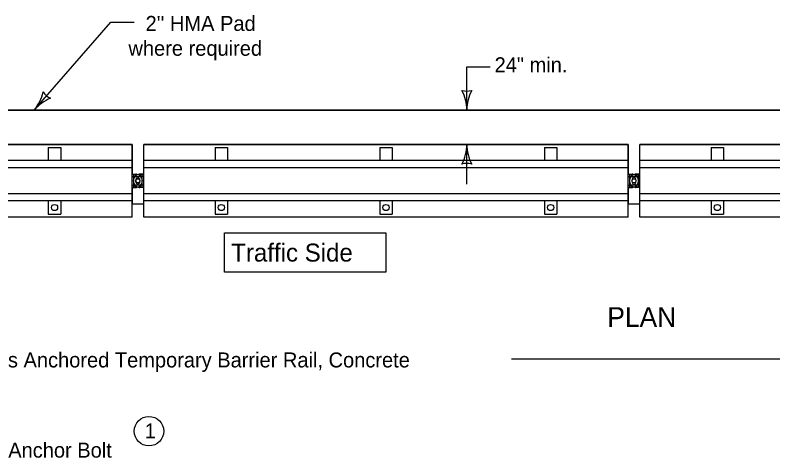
# Model space of a CAD drawing. Extents: x -2137026 to -2131464, y -2138478 to -2136524.
# Drawn here: x -2136307 to -2135538, y -2137950 to -2137501 of the extents above; entities that cross this region are included whole.
import ezdxf

# ---------------------------------------------------------------- set-up
doc = ezdxf.new("R2010")
doc.units = 0
for name, color, linetype in [('Level 2', 7, 'Continuous'), ('Level 3', 7, 'Continuous'), ('Level 41', 7, 'Continuous'), ('Level 9', 7, 'Continuous')]:
    doc.layers.add(name, color=color, linetype=linetype)

msp = doc.modelspace()

# ---------------------------------------------------------------- linework, layer by layer
at = {"layer": 'Level 2'}
for p, q in [((-2136287.84, -2137597.41), (-2136209.93, -2137508.05)), ((-2136209.93, -2137508.05), (-2136186.33, -2137508.05)), ((-2135848.76, -2137597.41), (-2135848.76, -2137553.36)), ((-2135848.76, -2137553.36), (-2135825.16, -2137553.36)), ((-2136188.5, -2137632.29), (-2136680.02, -2137632.29)), ((-2136188.5, -2137706.01), (-2136188.5, -2137632.29)), ((-2135685.1, -2137632.29), (-2136176.62, -2137632.29)), ((-2136176.62, -2137706.01), (-2136176.62, -2137632.29)), ((-2135848.76, -2137672.65), (-2135848.76, -2137632.29)), ((-2135685.1, -2137706.01), (-2135685.1, -2137632.29)), ((-2135181.7, -2137632.29), (-2135673.22, -2137632.29)), ((-2135673.22, -2137706.01), (-2135673.22, -2137632.29)), ((-2136188.5, -2137648.67), (-2136680.02, -2137648.67)), ((-2135685.1, -2137648.67), (-2136176.62, -2137648.67)), ((-2135181.7, -2137648.67), (-2135673.22, -2137648.67)), ((-2136188.5, -2137656.04), (-2136680.02, -2137656.04)), ((-2135685.1, -2137656.04), (-2136176.62, -2137656.04)), ((-2135181.7, -2137656.04), (-2135673.22, -2137656.04)), ((-2136188.5, -2137682.26), (-2136680.02, -2137682.26)), ((-2135685.1, -2137682.26), (-2136176.62, -2137682.26)), ((-2135181.7, -2137682.26), (-2135673.22, -2137682.26)), ((-2136188.5, -2137689.63), (-2136680.02, -2137689.63)), ((-2135685.1, -2137689.63), (-2136176.62, -2137689.63)), ((-2135181.7, -2137689.63), (-2135673.22, -2137689.63)), ((-2136188.5, -2137706.01), (-2136680.02, -2137706.01)), ((-2135685.1, -2137706.01), (-2136176.62, -2137706.01)), ((-2135181.7, -2137706.01), (-2135673.22, -2137706.01)), ((-2135803.58, -2137849.7), (-2134672.37, -2137849.7))]:
    msp.add_line(p, q, dxfattribs=at)
msp.add_circle((-2136171.3, -2137923.14), 15, dxfattribs=at)
for centre, radius, start, end in [((-2136320.19, -2137569.84), 42.5, 319.56638, 347.63887), ((-2136264.73, -2137570.28), 16.42, 211.83303, 247.29973), ((-2135848.76, -2137561.77), 16.42, 252.26665, 287.73335), ((-2135891.26, -2137597.41), 42.5, 360, 28.07249), ((-2135806.26, -2137597.41), 42.5, 151.92751, 180), ((-2136255.49, -2137624.97), 42.5, 111.49389, 139.56638), ((-2135891.26, -2137632.29), 42.5, 331.92751, 360), ((-2135806.26, -2137632.29), 42.5, 180, 208.07249), ((-2135848.76, -2137667.92), 16.42, 72.26665, 107.73335)]:
    msp.add_arc(centre, radius, start, end, dxfattribs=at)
at = {"layer": 'Level 41'}
for p, q in [((-2136273.44, -2137635.41), (-2136273.44, -2137648.67)), ((-2136273.44, -2137635.41), (-2136260.85, -2137635.41)), ((-2136260.85, -2137635.41), (-2136260.85, -2137648.67)), ((-2136104.27, -2137635.41), (-2136091.69, -2137635.41)), ((-2136104.27, -2137635.41), (-2136104.27, -2137648.67)), ((-2136091.69, -2137635.41), (-2136091.69, -2137648.67)), ((-2135937.15, -2137635.41), (-2135924.57, -2137635.41)), ((-2135937.15, -2137635.41), (-2135937.15, -2137648.67)), ((-2135924.57, -2137635.41), (-2135924.57, -2137648.67)), ((-2135770.04, -2137635.41), (-2135770.04, -2137648.67)), ((-2135770.04, -2137635.41), (-2135757.45, -2137635.41)), ((-2135757.45, -2137635.41), (-2135757.45, -2137648.67)), ((-2135600.87, -2137635.41), (-2135588.29, -2137635.41)), ((-2135600.87, -2137635.41), (-2135600.87, -2137648.67)), ((-2135588.29, -2137635.41), (-2135588.29, -2137648.67)), ((-2136188.5, -2137662.47), (-2136184.57, -2137662.47)), ((-2136188.5, -2137664.82), (-2136184.57, -2137664.82)), ((-2136176.62, -2137662.47), (-2136180.56, -2137662.47)), ((-2136176.62, -2137664.82), (-2136180.56, -2137664.82)), ((-2135685.1, -2137662.47), (-2135681.17, -2137662.47)), ((-2135685.1, -2137664.82), (-2135681.17, -2137664.82)), ((-2135673.22, -2137662.47), (-2135677.16, -2137662.47)), ((-2135673.22, -2137664.82), (-2135677.16, -2137664.82)), ((-2136188.5, -2137673.48), (-2136184.57, -2137673.48)), ((-2136176.62, -2137673.48), (-2136180.56, -2137673.48)), ((-2135685.1, -2137673.48), (-2135681.17, -2137673.48)), ((-2135673.22, -2137673.48), (-2135677.16, -2137673.48)), ((-2136188.5, -2137675.83), (-2136184.57, -2137675.83)), ((-2136176.62, -2137675.83), (-2136180.56, -2137675.83)), ((-2135685.1, -2137675.83), (-2135681.17, -2137675.83)), ((-2135673.22, -2137675.83), (-2135677.16, -2137675.83)), ((-2136273.44, -2137689.63), (-2136273.44, -2137702.89)), ((-2136260.85, -2137689.63), (-2136260.85, -2137702.89)), ((-2136104.27, -2137689.63), (-2136104.27, -2137702.89)), ((-2136091.69, -2137689.63), (-2136091.69, -2137702.89)), ((-2135937.15, -2137689.63), (-2135937.15, -2137702.89)), ((-2135924.57, -2137689.63), (-2135924.57, -2137702.89)), ((-2135770.04, -2137689.63), (-2135770.04, -2137702.89)), ((-2135757.45, -2137689.63), (-2135757.45, -2137702.89)), ((-2135600.87, -2137689.63), (-2135600.87, -2137702.89)), ((-2135588.29, -2137689.63), (-2135588.29, -2137702.89)), ((-2136273.44, -2137702.89), (-2136260.85, -2137702.89)), ((-2136104.27, -2137702.89), (-2136091.69, -2137702.89)), ((-2135937.15, -2137702.89), (-2135924.57, -2137702.89)), ((-2135770.04, -2137702.89), (-2135757.45, -2137702.89)), ((-2135600.87, -2137702.89), (-2135588.29, -2137702.89))]:
    msp.add_line(p, q, dxfattribs=at)
for centre in [(-2136267.14, -2137696.26), (-2136097.98, -2137696.26), (-2135930.86, -2137696.26), (-2135763.75, -2137696.26), (-2135594.58, -2137696.26)]:
    msp.add_circle(centre, 3.15, dxfattribs=at)
for centre, radius, start, end in [((-2136180.56, -2137669.15), 6.68, 90, 270), ((-2136180.56, -2137669.15), 4.33, 90, 270), ((-2136184.57, -2137669.15), 6.68, 270, 90), ((-2136184.57, -2137669.15), 4.33, 270, 90), ((-2135677.16, -2137669.15), 6.68, 90, 270), ((-2135677.16, -2137669.15), 4.33, 90, 270), ((-2135681.17, -2137669.15), 6.68, 270, 90), ((-2135681.17, -2137669.15), 4.33, 270, 90)]:
    msp.add_arc(centre, radius, start, end, dxfattribs=at)
at = {"layer": 'Level 9'}
for p, q in [((-2136691.9, -2137597.41), (-2134672.37, -2137597.41)), ((-2136191.5, -2137597.41), (-2136601.44, -2137597.41)), ((-2136601.44, -2137632.29), (-2136188.5, -2137632.29)), ((-2135673.22, -2137632.29), (-2135181.7, -2137632.29)), ((-2136188.5, -2137662.47), (-2136184.57, -2137662.47)), ((-2136186.66, -2137662.62), (-2136178.47, -2137662.62)), ((-2136186.66, -2137675.73), (-2136186.66, -2137662.62)), ((-2136183.13, -2137662.62), (-2136181.99, -2137662.62)), ((-2136180.56, -2137662.47), (-2136176.62, -2137662.47)), ((-2136178.47, -2137662.62), (-2136178.47, -2137675.73)), ((-2135685.1, -2137662.47), (-2135681.17, -2137662.47)), ((-2135683.26, -2137662.62), (-2135675.07, -2137662.62)), ((-2135683.26, -2137675.73), (-2135683.26, -2137662.62)), ((-2135679.74, -2137662.62), (-2135678.59, -2137662.62)), ((-2135677.16, -2137662.47), (-2135673.22, -2137662.47)), ((-2135675.07, -2137662.62), (-2135675.07, -2137675.73)), ((-2136184.57, -2137675.83), (-2136188.5, -2137675.83)), ((-2136178.47, -2137675.73), (-2136186.66, -2137675.73)), ((-2136181.74, -2137675.73), (-2136183.38, -2137675.73)), ((-2136176.62, -2137675.83), (-2136180.56, -2137675.83)), ((-2135681.17, -2137675.83), (-2135685.1, -2137675.83)), ((-2135675.07, -2137675.73), (-2135683.26, -2137675.73)), ((-2135678.34, -2137675.73), (-2135679.98, -2137675.73)), ((-2135673.22, -2137675.83), (-2135677.16, -2137675.83)), ((-2136188.5, -2137692.38), (-2136176.62, -2137692.38)), ((-2136188.5, -2137692.38), (-2136176.62, -2137692.38)), ((-2135685.1, -2137692.38), (-2135673.22, -2137692.38)), ((-2135685.1, -2137692.38), (-2135673.22, -2137692.38))]:
    msp.add_line(p, q, dxfattribs=at)
for points in [[(-2134672.37, -2137597.41), (-2136006.53, -2137597.41), (-2136191.5, -2137597.41), (-2136191.5, -2137597.41)], [(-2136191.5, -2137597.41), (-2136191.5, -2137597.41), (-2136191.5, -2137597.41)], [(-2136188.5, -2137632.29), (-2136188.5, -2137648.67), (-2136188.5, -2137656.04), (-2136188.5, -2137662.47)], [(-2136176.62, -2137662.47), (-2136176.62, -2137656.04), (-2136176.62, -2137648.67), (-2136176.62, -2137632.29)], [(-2136176.62, -2137632.29), (-2136006.53, -2137632.29), (-2135685.1, -2137632.29)], [(-2135685.1, -2137632.29), (-2135685.1, -2137648.67), (-2135685.1, -2137656.04), (-2135685.1, -2137662.47)], [(-2135673.22, -2137662.47), (-2135673.22, -2137656.04), (-2135673.22, -2137648.67), (-2135673.22, -2137632.29)], [(-2136188.5, -2137675.83), (-2136188.5, -2137682.26), (-2136188.5, -2137689.63), (-2136188.5, -2137692.38)], [(-2136176.62, -2137692.38), (-2136176.62, -2137689.63), (-2136176.62, -2137682.26), (-2136176.62, -2137675.83)], [(-2135685.1, -2137675.83), (-2135685.1, -2137682.26), (-2135685.1, -2137689.63), (-2135685.1, -2137692.38)], [(-2135673.22, -2137692.38), (-2135673.22, -2137689.63), (-2135673.22, -2137682.26), (-2135673.22, -2137675.83)]]:
    msp.add_lwpolyline(points, dxfattribs=at)
msp.add_lwpolyline([(-2136094.76, -2137721.98), (-2135931.11, -2137721.98), (-2135931.11, -2137761.98), (-2136094.76, -2137761.98)], close=True, dxfattribs=at)
for centre in [(-2136182.56, -2137669.17), (-2135679.16, -2137669.17)]:
    msp.add_circle(centre, 2.05, dxfattribs=at)
for centre, start, end in [((-2136184.57, -2137669.15), 77.60428, 90), ((-2136180.56, -2137669.15), 90, 102.39572), ((-2135681.17, -2137669.15), 77.60428, 90), ((-2135677.16, -2137669.15), 90, 102.39572), ((-2136184.57, -2137669.15), 270, 280.2309), ((-2136180.56, -2137669.15), 259.7691, 270), ((-2135681.17, -2137669.15), 270, 280.2309), ((-2135677.16, -2137669.15), 259.7691, 270)]:
    msp.add_arc(centre, 6.68, start, end, dxfattribs=at)

# ---------------------------------------------------------------- texts
at = {"layer": 'Level 2'}
msp.add_text('1', height=15.2, dxfattribs=at).set_placement((-2136175.67, -2137930.43))
at = {"layer": 'Level 3'}
for s, height, p in [("2'' HMA Pad", 15.2, (-2136174.74, -2137517.1)), ('where required', 15.2, (-2136192.13, -2137542.3)), ('24" min.', 15.2, (-2135820.58, -2137559.06)), ('Traffic Side', 18.24, (-2136087.82, -2137751.1)), ('PLAN', 20, (-2135706.2, -2137817.36)), ('4 Sections Anchored Temporary Barrier Rail, Concrete', 15.2, (-2136399.13, -2137858.5)), ('Rail Anchor Bolt', 15.2, (-2136354.76, -2137950))]:
    msp.add_text(s, height=height, dxfattribs=at).set_placement(p)

doc.saveas('drawing.dxf')
